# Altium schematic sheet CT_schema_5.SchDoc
size 371 x 245 mm
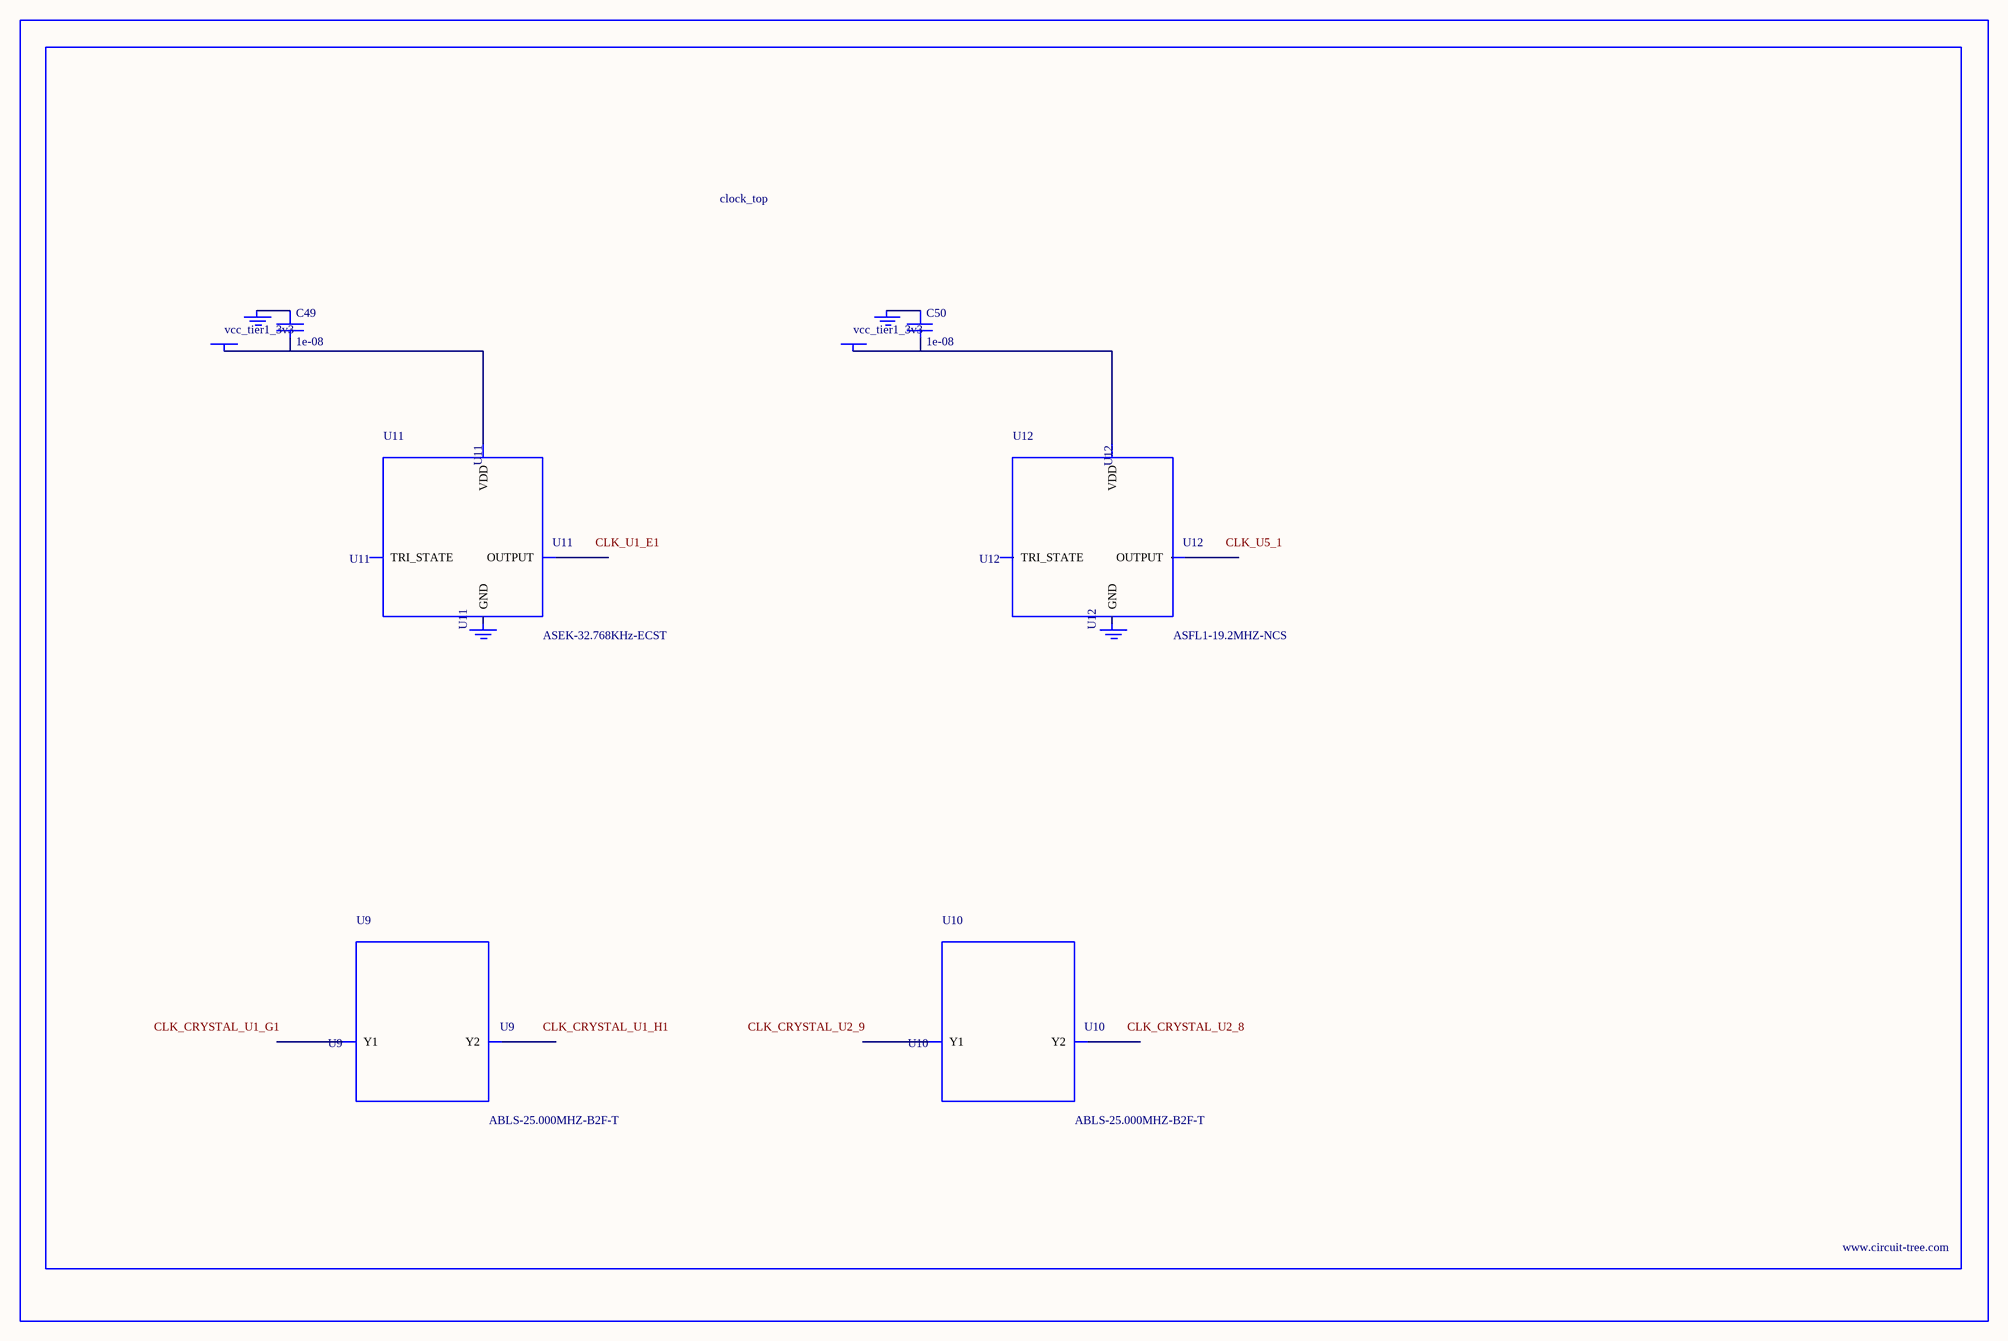
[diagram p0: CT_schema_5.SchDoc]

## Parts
BORDER4  (no value)
C49  1e-08  [C0402]
C50  1e-08  [C0402]
GND_INSTANCE_4_0  (no value)
GND_INSTANCE_4_1  (no value)
GND_INSTANCE_4_2  (no value)
GND_INSTANCE_4_3  (no value)
POWER_INSTANCE_4_0  vcc_tier1_3v3
POWER_INSTANCE_4_1  vcc_tier1_3v3
U9  ABLS-25.000MHZ-B2F-T  [ABLS-25.000MHZ-B2F-T]
U10  ABLS-25.000MHZ-B2F-T  [ABLS-25.000MHZ-B2F-T]
U11  ASEK-32.768KHz-ECST  [ASEK]
U12  ASFL1-19.2MHZ-NCS  [ASFL1]

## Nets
NetC49_1: C49.1 GND_INSTANCE_4_0.0(GND)
NetC49_2: C49.2 POWER_INSTANCE_4_0.0(PWR) U11.4(VDD)
NetC50_1: C50.1 GND_INSTANCE_4_2.0(GND)
NetC50_2: C50.2 POWER_INSTANCE_4_1.0(PWR) U12.4(VDD)

Not connected (* = marked no-connect by the designer): GND_INSTANCE_4_1 0(GND); GND_INSTANCE_4_3 0(GND); U9 1(Y1) 2(Y2); U10 1(Y1) 2(Y2); U11 1(TRI_STATE) 2(GND) 3(OUTPUT); U12 1(TRI_STATE) 2(GND) 3(OUTPUT)

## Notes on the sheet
- Labels drawn without touching a wire or pin: CLK_CRYSTAL_U1_G1, CLK_CRYSTAL_U1_H1, CLK_CRYSTAL_U2_8, CLK_CRYSTAL_U2_9, CLK_U1_E1, CLK_U5_1

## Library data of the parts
BORDER4 = BORDER_PAGE4
C49 C50 = C0402C103K3RAC
GND_INSTANCE_4_0-GND_INSTANCE_4_3 = GND
POWER_INSTANCE_4_0 POWER_INSTANCE_4_1 = PWR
